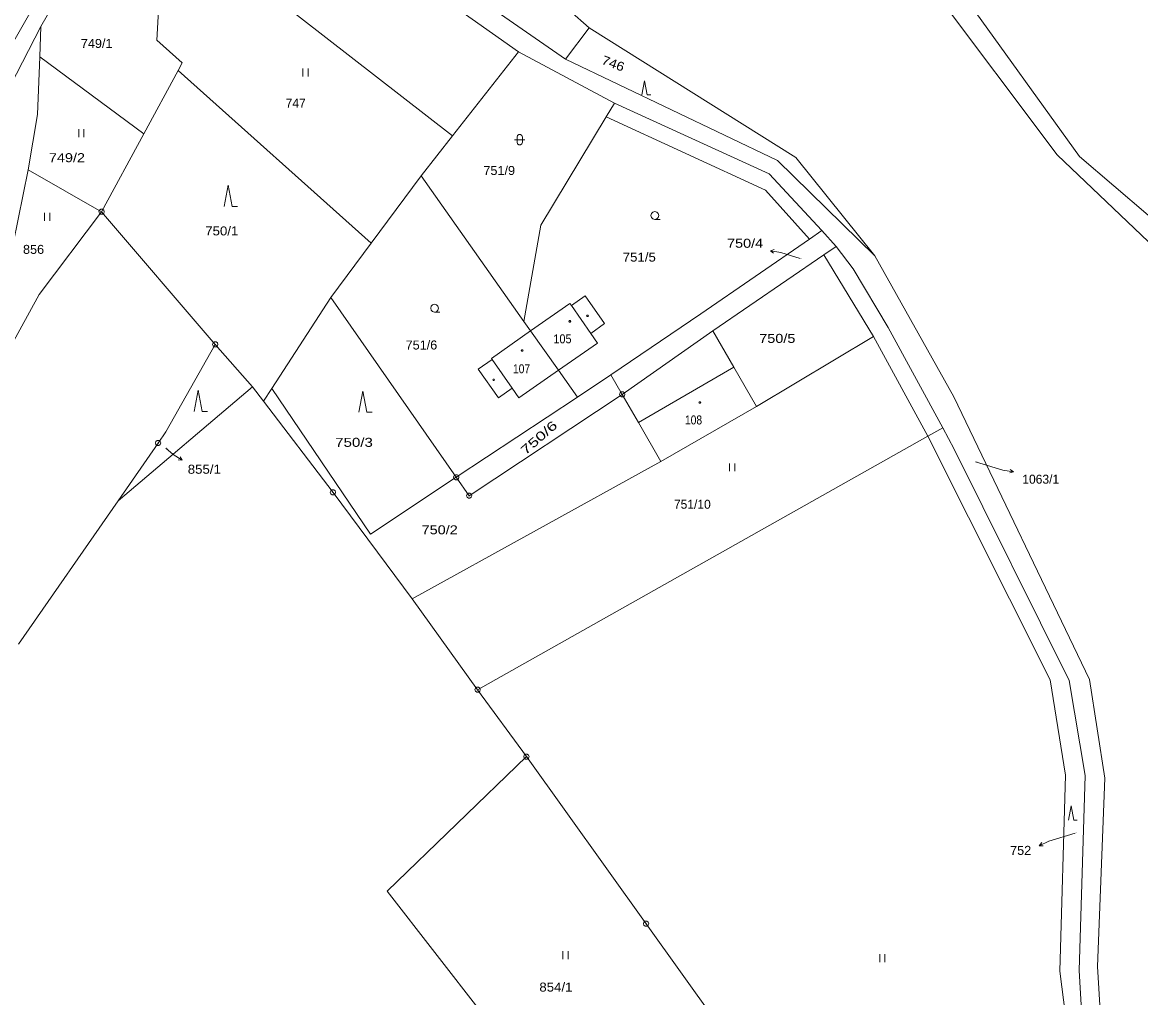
# Model space of a CAD drawing. Extents: x -687390 to -684106, y -954833 to -951648.
# Drawn here: x -687191.2 to -686980, y -953586.1 to -953401.9 of the extents above; entities that cross this region are included whole.
import ezdxf
from ezdxf.enums import TextEntityAlignment as Align

# ---------------------------------------------------------------- set-up
doc = ezdxf.new("R2010")
doc.units = 0
doc.header["$LTSCALE"] = 0.68
for name, color, linetype, lineweight in [('1', 7, 'Continuous', 13), ('3', 7, 'Continuous', 13), ('4', 7, 'Continuous', 13), ('5', 7, 'Continuous', 13), ('7', 7, 'Continuous', 13), ('8', 7, 'Continuous', 13)]:
    doc.layers.add(name, color=color, linetype=linetype, lineweight=lineweight)
doc.layers.add('2', color=7, linetype='Continuous')

msp = doc.modelspace()

# ---------------------------------------------------------------- linework, layer by layer
at = {"layer": '1'}
for p, q in [((-687187.64, -953402.72), (-687175.99, -953382.19)), ((-687145.16, -953395.99), (-687109.92, -953423.36)), ((-687187.64, -953402.72), (-687196.41, -953419.69)), ((-687168.23, -953423.01), (-687187.87, -953408.43)), ((-687080.91, -953419.77), (-687079.36, -953417.19)), ((-687190.07, -953429.77), (-687188.31, -953419.34)), ((-687093.29, -953440.24), (-687080.91, -953419.77)), ((-687115.84, -953430.9), (-687096.49, -953458.41)), ((-687096.49, -953458.41), (-687093.29, -953440.24)), ((-687042.58, -953442.91), (-687040.22, -953441.28)), ((-687040.22, -953441.28), (-687037.5, -953444.26)), ((-687042.58, -953442.91), (-687063.04, -953456.96)), ((-687037.5, -953444.26), (-687034.3, -953448.52)), ((-687030.2, -953446.04), (-687015.31, -953472.69)), ((-687034.3, -953448.52), (-687027.73, -953459.58)), ((-687144.08, -953471.12), (-687132.92, -953453.91)), ((-687109.24, -953487.85), (-687132.92, -953453.91)), ((-687084.88, -953453.57), (-687087.51, -953455.41)), ((-687081.23, -953458.83), (-687084.88, -953453.57)), ((-687087.77, -953455.04), (-687095.21, -953460.23)), ((-687087.51, -953455.41), (-687087.77, -953455.04)), ((-687096.49, -953458.41), (-687095.21, -953460.23)), ((-687080.05, -953468.5), (-687063.04, -953456.96)), ((-687095.21, -953460.23), (-687102.59, -953465.41)), ((-687095.21, -953460.23), (-687089.96, -953467.65)), ((-687083.86, -953460.68), (-687081.23, -953458.83)), ((-687082.6, -953462.5), (-687083.86, -953460.68)), ((-687077.9, -953472.22), (-687060.83, -953460.19)), ((-687060.83, -953460.19), (-687056.84, -953467.09)), ((-687017.4, -953478.55), (-687027.73, -953459.58)), ((-687089.96, -953467.65), (-687082.6, -953462.5)), ((-687052.57, -953474.47), (-687030.45, -953461.29)), ((-687030.45, -953461.29), (-687020.19, -953480.11)), ((-687102.44, -953465.63), (-687105.08, -953467.46)), ((-687102.59, -953465.41), (-687102.44, -953465.63)), ((-687056.84, -953467.09), (-687052.57, -953474.47)), ((-687105.08, -953467.46), (-687101.29, -953472.87)), ((-687089.96, -953467.65), (-687097.4, -953472.84)), ((-687089.96, -953467.65), (-687086.38, -953472.7)), ((-687080.05, -953468.5), (-687086.38, -953472.7)), ((-687080.05, -953468.5), (-687077.9, -953472.22)), ((-687147.69, -953470.76), (-687145.62, -953473.5)), ((-687144.08, -953471.12), (-687145.62, -953473.5)), ((-687144.08, -953471.12), (-687125.41, -953498.57)), ((-687101.29, -953472.87), (-687098.67, -953471.03)), ((-687098.67, -953471.03), (-687097.4, -953472.84)), ((-687086.38, -953472.7), (-687109.24, -953487.85)), ((-687077.9, -953472.22), (-687074.85, -953477.51)), ((-686989.72, -953526.06), (-687015.31, -953472.69)), ((-687145.62, -953473.5), (-687132.51, -953490.71)), ((-687052.57, -953474.47), (-687070.59, -953484.88)), ((-687070.59, -953484.88), (-687074.85, -953477.51)), ((-687164.09, -953479.29), (-687165.54, -953481.39)), ((-687173.1, -953492.29), (-687165.54, -953481.39)), ((-686993.55, -953526.22), (-687015.23, -953482.54)), ((-687109.24, -953487.85), (-687125.41, -953498.57)), ((-687117.58, -953510.83), (-687132.51, -953490.71)), ((-686993.55, -953526.22), (-686990.49, -953544.17)), ((-687095.98, -953540.62), (-687073.39, -953572.18)), ((-686990.49, -953544.17), (-686991.62, -953580.99)), ((-687122.28, -953566.01), (-687104.26, -953589.16)), ((-687054.67, -953598.36), (-687073.39, -953572.18)), ((-686995.32, -953581.1), (-686994.2, -953589.53)), ((-686989.73, -953615.03), (-686991.62, -953580.99))]:
    msp.add_line(p, q, dxfattribs=at)
for points in [[(-687110.94, -953368.68), (-687111.28, -953373.85), (-687098.98, -953389.84), (-687084.17, -953402.97)], [(-687111.28, -953373.85), (-687110.64, -953384.99), (-687108.23, -953395.23), (-687088.63, -953408.91), (-687084.17, -953402.97)], [(-687037.88, -953375.05), (-687023.89, -953388.57), (-687013.39, -953396.86), (-686991.55, -953427.26), (-686972.13, -953443.92), (-686960.08, -953450.71), (-686939.95, -953457.51), (-686924.36, -953467.19), (-686912.54, -953478.09), (-686903.13, -953503.34), (-686894.42, -953534.14), (-686888.97, -953583.77)], [(-687178.53, -953380.51), (-687192.76, -953405.49), (-687218.75, -953460.74), (-687244.43, -953497.5), (-687254.77, -953515.5)], [(-687178.53, -953380.51), (-687175.99, -953382.19), (-687164.9, -953389.57), (-687165.8, -953405.33), (-687160.97, -953409.57)], [(-687117.09, -953384.72), (-687113.48, -953387.86), (-687111.12, -953397.85), (-687097.46, -953407.51)], [(-687030.33, -953387.15), (-687019.11, -953395.83), (-686995.77, -953426.94), (-686974.61, -953447.17), (-686958.03, -953454.71), (-686941.83, -953460.86), (-686926.64, -953470), (-686915.85, -953479.55), (-686904.42, -953510.15), (-686897.13, -953538.3), (-686894.86, -953562.01)], [(-687187.64, -953402.72), (-687187.87, -953408.43), (-687188.31, -953419.34)], [(-687084.17, -953402.97), (-687045.15, -953427.45), (-687030.2, -953446.04)], [(-687115.84, -953430.9), (-687109.92, -953423.36), (-687097.46, -953407.51)], [(-687097.46, -953407.51), (-687079.36, -953417.19), (-687050.14, -953430.54), (-687040.22, -953441.28)], [(-687125.3, -953443.64), (-687161.75, -953411.02), (-687160.97, -953409.57)], [(-687030.2, -953446.04), (-687048.61, -953428.05), (-687088.63, -953408.91)], [(-687176.19, -953437.73), (-687168.23, -953423.01), (-687161.75, -953411.02)], [(-687228.11, -953518.77), (-687216.87, -953492.55), (-687201.57, -953478.07), (-687187.98, -953453.34), (-687176.19, -953437.73), (-687190.07, -953429.77), (-687193.81, -953448.45), (-687203.76, -953471.34), (-687216.87, -953492.55)], [(-687115.84, -953430.9), (-687125.3, -953443.64), (-687132.92, -953453.91)], [(-687176.19, -953437.73), (-687154.74, -953462.77), (-687164.09, -953479.29)], [(-687060.83, -953460.19), (-687039.84, -953445.87), (-687037.5, -953444.26)], [(-687154.74, -953462.77), (-687147.69, -953470.76), (-687173.1, -953492.29), (-687191.88, -953519.4)], [(-687109.24, -953487.85), (-687106.8, -953491.35), (-687077.9, -953472.22)], [(-687105.22, -953527.98), (-687020.19, -953480.11), (-687017.4, -953478.55), (-687015.23, -953482.54)], [(-686995.32, -953581.1), (-686994.21, -953544.1), (-686997.09, -953526.13), (-687020.19, -953480.11)], [(-687070.59, -953484.88), (-687117.58, -953510.83), (-687105.22, -953527.98)], [(-686983.6, -953622.05), (-686986.01, -953615.7), (-686988.15, -953580.23), (-686986.8, -953544.67), (-686989.72, -953526.06)], [(-687122.28, -953566.01), (-687095.98, -953540.62), (-687105.22, -953527.98)]]:
    msp.add_lwpolyline(points, dxfattribs=at)
at = {"layer": '3'}
for p, q in [((-687138.21, -953410.69), (-687138.21, -953412.19)), ((-687137.21, -953412.19), (-687137.21, -953410.69)), ((-687180.52, -953422.12), (-687180.52, -953423.62)), ((-687179.52, -953423.62), (-687179.52, -953422.12)), ((-687186.98, -953437.91), (-687186.98, -953439.41)), ((-687185.98, -953439.41), (-687185.98, -953437.91)), ((-687057.67, -953485.23), (-687057.67, -953486.73)), ((-687056.67, -953486.73), (-687056.67, -953485.23)), ((-687089.13, -953577.36), (-687089.13, -953578.86)), ((-687088.13, -953578.86), (-687088.13, -953577.36)), ((-687029.3, -953577.95), (-687029.3, -953579.45)), ((-687028.3, -953579.45), (-687028.3, -953577.95))]:
    msp.add_line(p, q, dxfattribs=at)
for points in [[(-687074.202, -953415.64), (-687073.7, -953412.96), (-687073.198, -953415.64), (-687072.528, -953415.64)], [(-687098.27, -953424.1), (-687097, -953424.1), (-687096.27, -953424.1)], [(-687153.05, -953436.7), (-687152.3, -953432.7), (-687151.55, -953436.7), (-687150.55, -953436.7)], [(-687071.73, -953439.15), (-687072.11, -953439.05), (-687072.38, -953438.78), (-687072.48, -953438.41), (-687072.38, -953438.04), (-687072.11, -953437.77), (-687071.74, -953437.67), (-687071.37, -953437.77), (-687071.1, -953438.04), (-687071, -953438.42), (-687071.1, -953438.8), (-687071.37, -953439.07), (-687071.75, -953439.17), (-687070.75, -953439.17)], [(-687113.32, -953456.67), (-687113.7, -953456.57), (-687113.97, -953456.3), (-687114.07, -953455.93), (-687113.97, -953455.56), (-687113.7, -953455.29), (-687113.33, -953455.19), (-687112.96, -953455.29), (-687112.69, -953455.56), (-687112.59, -953455.94), (-687112.69, -953456.32), (-687112.96, -953456.59), (-687113.34, -953456.69), (-687112.34, -953456.69)], [(-687158.73, -953475.41), (-687157.98, -953471.41), (-687157.23, -953475.41), (-687156.23, -953475.41)], [(-687127.63, -953475.58), (-687126.88, -953471.58), (-687126.13, -953475.58), (-687125.13, -953475.58)], [(-686993.682, -953552.59), (-686993.18, -953549.91), (-686992.678, -953552.59), (-686992.008, -953552.59)]]:
    msp.add_lwpolyline(points, dxfattribs=at)
msp.add_lwpolyline([(-687097.77, -953423.6), (-687097.67, -953423.31), (-687097.42, -953423.13), (-687097.11, -953423.13), (-687096.86, -953423.31), (-687096.76, -953423.6), (-687096.76, -953424.6), (-687096.86, -953424.89), (-687097.11, -953425.07), (-687097.42, -953425.07), (-687097.67, -953424.89), (-687097.77, -953424.6)], close=True, dxfattribs=at)
at = {"layer": '4'}
for p, q in [((-687050.85, -953433.61), (-687080.91, -953419.77)), ((-687042.58, -953442.91), (-687050.85, -953433.61)), ((-687039.84, -953445.87), (-687030.45, -953461.29)), ((-687087.51, -953455.41), (-687083.86, -953460.68)), ((-687102.44, -953465.63), (-687098.67, -953471.03)), ((-687074.85, -953477.51), (-687056.84, -953467.09))]:
    msp.add_line(p, q, dxfattribs=at)
at = {"layer": '5'}
for points in [[(-687087.71, -953458.27), (-687087.62, -953458.42), (-687087.71, -953458.57), (-687087.89, -953458.57), (-687087.98, -953458.42), (-687087.89, -953458.27)], [(-687084.38, -953457.22), (-687084.29, -953457.37), (-687084.38, -953457.52), (-687084.56, -953457.52), (-687084.65, -953457.37), (-687084.56, -953457.22)], [(-687096.7, -953463.76), (-687096.61, -953463.91), (-687096.7, -953464.06), (-687096.88, -953464.06), (-687096.97, -953463.91), (-687096.88, -953463.76)], [(-687102.09, -953469.3), (-687102, -953469.45), (-687102.09, -953469.6), (-687102.27, -953469.6), (-687102.36, -953469.45), (-687102.27, -953469.3)], [(-687063.18, -953473.58), (-687063.09, -953473.73), (-687063.18, -953473.88), (-687063.36, -953473.88), (-687063.45, -953473.73), (-687063.36, -953473.58)]]:
    msp.add_lwpolyline(points, close=True, dxfattribs=at)
at = {"layer": '7'}
for p, q in [((-687049.945, -953445.084), (-687047.96, -953445.4)), ((-687044.31, -953446.52), (-687047.96, -953445.4)), ((-687164.1, -953482.36), (-687162.7, -953483.55)), ((-687160.999, -953484.62), (-687162.7, -953483.55)), ((-687011.19, -953484.94), (-687006.03, -953486.5)), ((-687004.043, -953486.805), (-687006.03, -953486.5)), ((-686992.38, -953555.05), (-686997.35, -953556.59)), ((-686999.167, -953557.45), (-686997.35, -953556.59))]:
    msp.add_line(p, q, dxfattribs=at)
for points in [[(-687049.336, -953445.52), (-687049.945, -953445.084), (-687049.231, -953444.859)], [(-687161.387, -953483.98), (-687160.999, -953484.62), (-687161.744, -953484.547)], [(-687004.655, -953486.372), (-687004.043, -953486.805), (-687004.756, -953487.035)], [(-686998.418, -953557.466), (-686999.167, -953557.45), (-686998.704, -953556.861)]]:
    msp.add_lwpolyline(points, dxfattribs=at)
at = {"layer": '8'}
for p, q in [((-687176.31, -953437.73), (-687176.07, -953437.73)), ((-687154.86, -953462.77), (-687154.62, -953462.77)), ((-687078.02, -953472.22), (-687077.78, -953472.22)), ((-687165.66, -953481.39), (-687165.42, -953481.39)), ((-687109.36, -953487.85), (-687109.12, -953487.85)), ((-687132.63, -953490.71), (-687132.39, -953490.71)), ((-687106.92, -953491.35), (-687106.68, -953491.35)), ((-687105.34, -953527.98), (-687105.1, -953527.98)), ((-687096.1, -953540.62), (-687095.86, -953540.62)), ((-687073.51, -953572.18), (-687073.27, -953572.18))]:
    msp.add_line(p, q, dxfattribs=at)
for points in [[(-687176.04, -953437.25), (-687175.79, -953437.43), (-687175.69, -953437.72), (-687175.79, -953438.01), (-687176.04, -953438.19), (-687176.35, -953438.19), (-687176.6, -953438.01), (-687176.7, -953437.72), (-687176.6, -953437.43), (-687176.35, -953437.25)], [(-687154.59, -953462.29), (-687154.34, -953462.47), (-687154.24, -953462.76), (-687154.34, -953463.05), (-687154.59, -953463.23), (-687154.9, -953463.23), (-687155.15, -953463.05), (-687155.25, -953462.76), (-687155.15, -953462.47), (-687154.9, -953462.29)], [(-687077.75, -953471.74), (-687077.5, -953471.92), (-687077.4, -953472.21), (-687077.5, -953472.5), (-687077.75, -953472.68), (-687078.06, -953472.68), (-687078.31, -953472.5), (-687078.41, -953472.21), (-687078.31, -953471.92), (-687078.06, -953471.74)], [(-687165.39, -953480.91), (-687165.14, -953481.09), (-687165.04, -953481.38), (-687165.14, -953481.67), (-687165.39, -953481.85), (-687165.7, -953481.85), (-687165.95, -953481.67), (-687166.05, -953481.38), (-687165.95, -953481.09), (-687165.7, -953480.91)], [(-687109.09, -953487.37), (-687108.84, -953487.55), (-687108.74, -953487.84), (-687108.84, -953488.13), (-687109.09, -953488.31), (-687109.4, -953488.31), (-687109.65, -953488.13), (-687109.75, -953487.84), (-687109.65, -953487.55), (-687109.4, -953487.37)], [(-687132.36, -953490.23), (-687132.11, -953490.41), (-687132.01, -953490.7), (-687132.11, -953490.99), (-687132.36, -953491.17), (-687132.67, -953491.17), (-687132.92, -953490.99), (-687133.02, -953490.7), (-687132.92, -953490.41), (-687132.67, -953490.23)], [(-687106.65, -953490.87), (-687106.4, -953491.05), (-687106.3, -953491.34), (-687106.4, -953491.63), (-687106.65, -953491.81), (-687106.96, -953491.81), (-687107.21, -953491.63), (-687107.31, -953491.34), (-687107.21, -953491.05), (-687106.96, -953490.87)], [(-687105.07, -953527.5), (-687104.82, -953527.68), (-687104.72, -953527.97), (-687104.82, -953528.26), (-687105.07, -953528.44), (-687105.38, -953528.44), (-687105.63, -953528.26), (-687105.73, -953527.97), (-687105.63, -953527.68), (-687105.38, -953527.5)], [(-687095.83, -953540.14), (-687095.58, -953540.32), (-687095.48, -953540.61), (-687095.58, -953540.9), (-687095.83, -953541.08), (-687096.14, -953541.08), (-687096.39, -953540.9), (-687096.49, -953540.61), (-687096.39, -953540.32), (-687096.14, -953540.14)], [(-687073.24, -953571.7), (-687072.99, -953571.88), (-687072.89, -953572.17), (-687072.99, -953572.46), (-687073.24, -953572.64), (-687073.55, -953572.64), (-687073.8, -953572.46), (-687073.9, -953572.17), (-687073.8, -953571.88), (-687073.55, -953571.7)]]:
    msp.add_lwpolyline(points, close=True, dxfattribs=at)

# ---------------------------------------------------------------- texts
at = {"layer": '2'}
for s, height, width, p in [('749/1', 1.7, 1.05, (-687180.115, -953406.78)), ('749/2', 1.7, 1.2, (-687186.155, -953428.35)), ('751/9', 1.7, 1.05, (-687104.115, -953430.77)), ('750/1', 1.7, 1.1, (-687156.635, -953442.18)), ('856', 1.7, 1.05, (-687191.035, -953445.67)), ('751/5', 1.7, 1.1, (-687077.815, -953447.13)), ('750/4', 0.1, 1.2, (-687044.282, -953446.52)), ('750/5', 1.7, 1.2, (-687052.045, -953462.48)), ('751/6', 1.7, 1.05, (-687118.805, -953463.73)), ('105', 1.7, 0.9, (-687090.895, -953462.56)), ('107', 1.7, 0.85, (-687098.525, -953468.22)), ('108', 1.7, 0.85, (-687066.055, -953477.88)), ('750/3', 1.7, 1.25, (-687132.095, -953482.11)), ('855/1', 0.1, 1.1, (-687164.072, -953482.36)), ('750/2', 1.7, 1.2, (-687115.785, -953498.63)), ('752', 0.1, 1.05, (-686992.352, -953555.05)), ('854/1', 1.7, 1.1, (-687093.555, -953584.99))]:
    msp.add_text(s, height=height, dxfattribs=dict(at, width=width)).set_placement(p)
for s, rotation, width, p in [('746', 339.592, 1.15, (-687081.955, -953409.746)), ('750/6', 41.31, 1.45, (-687096.173, -953483.737))]:
    msp.add_text(s, height=1.7, rotation=rotation, dxfattribs=dict(at, width=width)).set_placement(p)
for s, height, p in [('747', 1.7, (-687141.445, -953418.05)), ('1063/1', 0.1, (-687011.144, -953484.94)), ('751/10', 1.7, (-687068.145, -953493.8))]:
    msp.add_text(s, height=height, dxfattribs=at).set_placement(p)
at = {"layer": '7'}
for s, width, p in [('750/4', 1.2, (-687051.296, -953444.51)), ('752', 1.05, (-687000.696, -953559.17))]:
    msp.add_text(s, height=1.7, dxfattribs=dict(at, width=width)).set_placement(p, align=Align.RIGHT)
at = {"layer": '7', "width": 1.1}
msp.add_text('855/1', height=1.7, dxfattribs=at).set_placement((-687159.935, -953487.19))
at = {"layer": '7'}
msp.add_text('1063/1', height=1.7, dxfattribs=at).set_placement((-687002.375, -953489.07))

doc.saveas('drawing.dxf')
